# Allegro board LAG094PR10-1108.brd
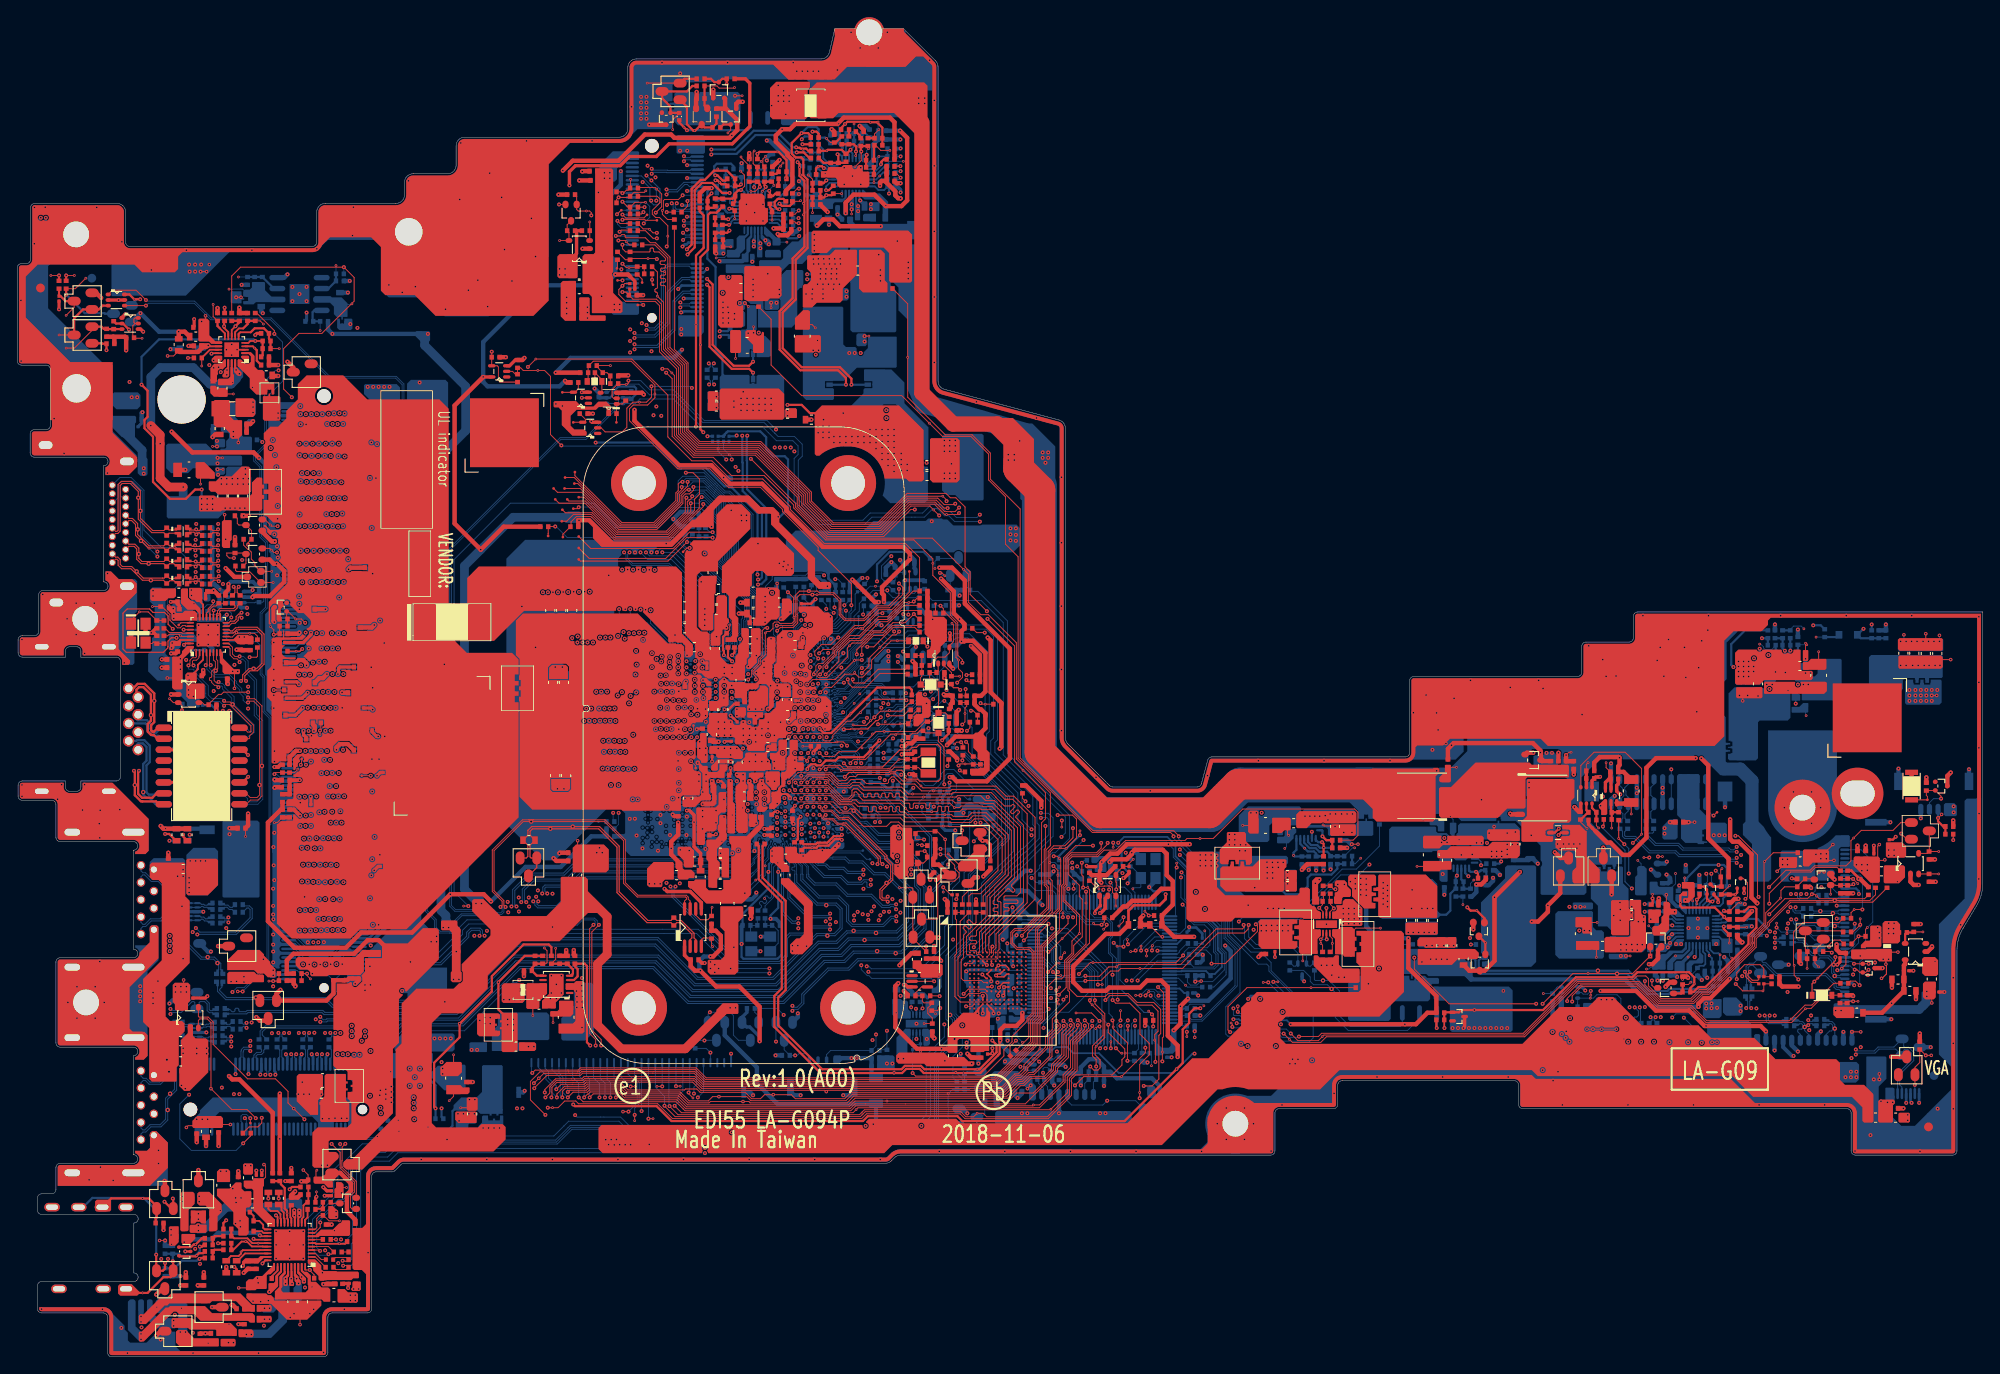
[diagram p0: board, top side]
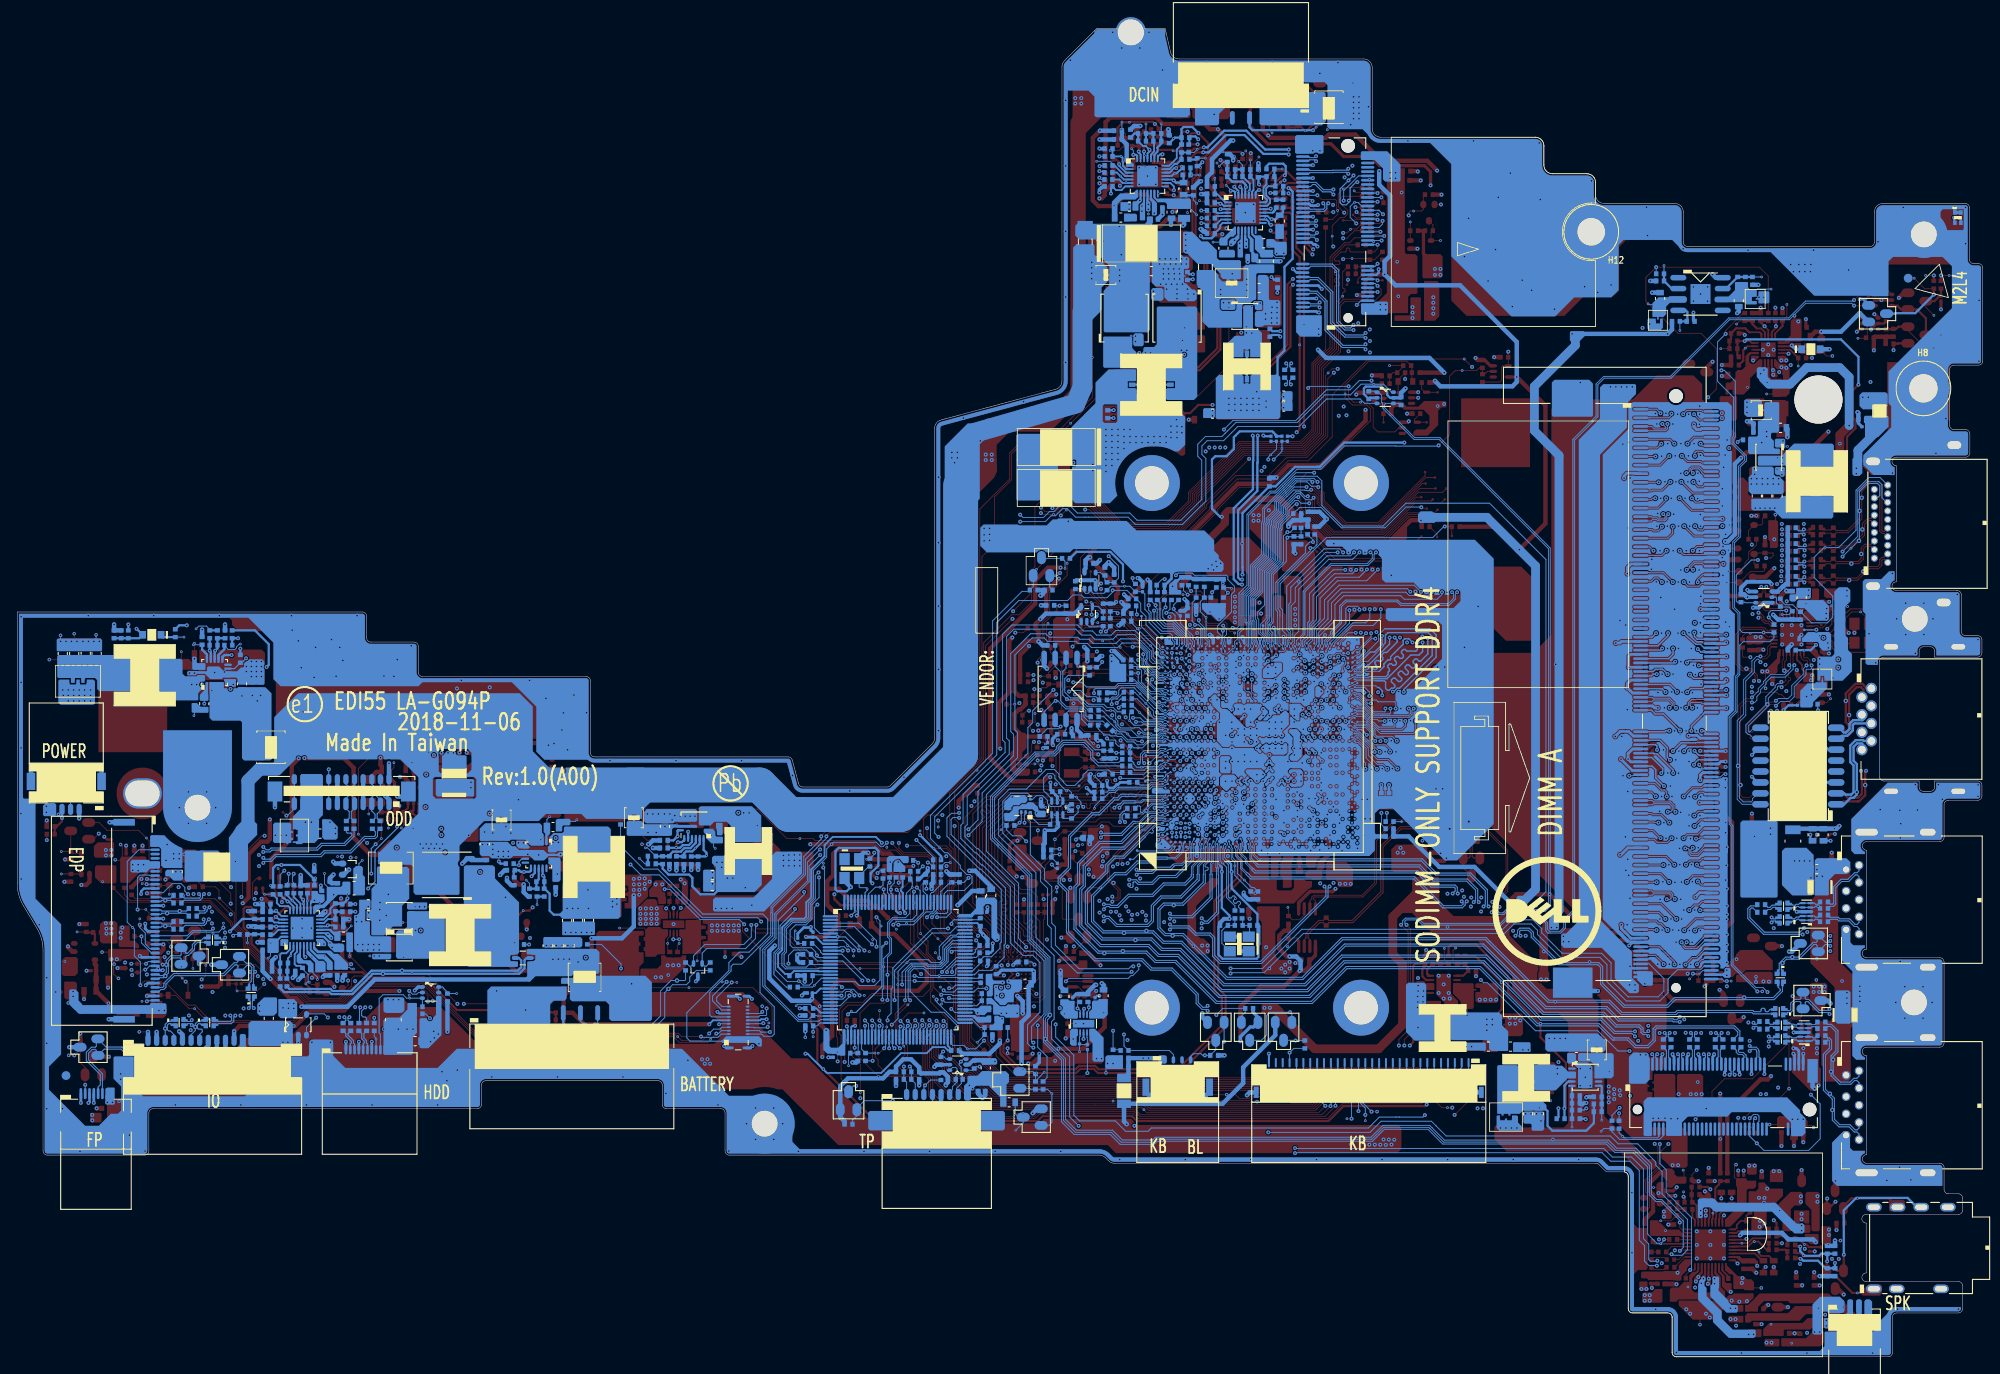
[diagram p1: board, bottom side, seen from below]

Outline 228.4 x 154.4 mm; copper layers: TOP, VCC, IN1, IN2, GND, BOTTOM. Coordinates in mm from the lower left corner of the outline.

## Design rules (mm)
net group CLK_SMB: nets CLK_SMB DAT_SMB
net group CLOCK: nets LPC_CLK_EC SUSCLK
net group DDR_M0_CLK0: nets DDR_M0_CLK0 DDR_M0_CLK#0
net group DDR_M0_CLK1: nets DDR_M0_CLK1 DDR_M0_CLK#1
net group DDR_M0_DQS0: nets DDR_M0_DQS0 DDR_M0_DQS#0
net group DDR_M0_DQS1: nets DDR_M0_DQS1 DDR_M0_DQS#1
net group DDR_M0_DQS2: nets DDR_M0_DQS2 DDR_M0_DQS#2
net group DDR_M0_DQS3: nets DDR_M0_DQS3 DDR_M0_DQS#3
net group DDR_M0_DQS4: nets DDR_M0_DQS4 DDR_M0_DQS#4
net group DDR_M0_DQS5: nets DDR_M0_DQS5 DDR_M0_DQS#5
net group DDR_M0_DQS6: nets DDR_M0_DQS6 DDR_M0_DQS#6
net group DDR_M0_DQS7: nets DDR_M0_DQS7 DDR_M0_DQS#7
net group DDR_RCOMP: nets DDR_M0_RCOMP DDR_M1_RCOMP
net group DIFFPAIR0: nets THM_SML1_CLK THM_SML1_DATA
net group DMIC: nets DMIC_CLK DMIC_DATA
net group EC_SMB_CK2: nets EC_SMB_CK2 EC_SMB_DA2
net group I2C_SCL_TP: nets I2C_SCL_TP I2C_SDA_TP
net group LAN_MDI2: nets LAN_MDIN2 LAN_MDIP2
net group LAN_MDI3: nets LAN_MDIN3 LAN_MDIP3
net group NCT7718_DX: nets NCT7718_DXN NCT7718_DXP
net group RJ45_MDI2: nets RJ45_MDIN2 RJ45_MDIP2
net group RJ45_MDI3: nets RJ45_MDIN3 RJ45_MDIP3
net group SENSE: nets VCC_VCGI_SENSE_N VCC_VCGI_SENSE_P
net group SOC_DP1_CTRL_CLK: nets SOC_DP1_CTRL_CLK SOC_DP1_CTRL_DATA
net group SOC_SMBCLK: nets SOC_SMBCLK SOC_SMBDATA
net group VNN_SENSE: nets VNN_SENSE VNN_SENSE_N
net group 15: nets DMIC_CLK_EDP EMMC_0_CLK HDA_BIT_CLK_R I2C_5_SCL REFCLK_CNV REFCLK_CNV_R SOC_SPI_CLK_R
net group AUDIO: nets HPOUT_L HPOUT_R LINE1-L_C LINE1-L_R N38607828
net group CNVI: nets CNVI_WGR_CLK_DN CNVI_WGR_CLK_DP CNVI_WGR_DATA0_DN CNVI_WGR_DATA0_DP CNVI_WGR_DATA1_DN CNVI_WGR_DATA1_DP CNVI_WT_CLK_DN CNVI_WT_CLK_DP CNVI_WT_DATA0_DN CNVI_WT_DATA0_DP CNVI_WT_DATA1_DN CNVI_WT_DATA1_DP
net group CNVI-OTHER: nets CLKREQ_CNV# CNV_BRI_PRX_DTX CNV_BRI_PTX_DRX CNV_RF_RESET# CNV_RGI_PRX_DTX CNV_RGI_PTX_DRX
net group DDR_CMD: nets DDR_M0_ACT# DDR_M0_ALERT# DDR_M0_BA0 DDR_M0_BA1 DDR_M0_BG0 DDR_M0_BG1 DDR_M0_CS#0 DDR_M0_CS#1 DDR_M0_MA0 DDR_M0_MA1 DDR_M0_MA2 DDR_M0_MA3 DDR_M0_MA4 DDR_M0_MA5 DDR_M0_MA6 DDR_M0_MA7 DDR_M0_MA8 DDR_M0_MA9 DDR_M0_MA10 DDR_M0_MA11 DDR_M0_MA12 DDR_M0_MA13 DDR_M0_MA14_WE# DDR_M0_MA15_CAS# DDR_M0_MA16_RAS#
net group DDR_CTL: nets DDR_M0_CKE0 DDR_M0_CKE1 DDR_M0_ODT0 DDR_M0_ODT1
net group DDR_D0: nets DDR_M0_D0 DDR_M0_D1 DDR_M0_D2 DDR_M0_D3 DDR_M0_D4 DDR_M0_D5 DDR_M0_D6 DDR_M0_D7
net group DDR_D1: nets DDR_M0_D8 DDR_M0_D9 DDR_M0_D10 DDR_M0_D11 DDR_M0_D12 DDR_M0_D13 DDR_M0_D14 DDR_M0_D15
net group DDR_D2: nets DDR_M0_D16 DDR_M0_D17 DDR_M0_D18 DDR_M0_D19 DDR_M0_D20 DDR_M0_D21 DDR_M0_D22 DDR_M0_D23
net group DDR_D3: nets DDR_M0_D24 DDR_M0_D25 DDR_M0_D26 DDR_M0_D27 DDR_M0_D28 DDR_M0_D29 DDR_M0_D30 DDR_M0_D31
net group DDR_D4: nets DDR_M0_D32 DDR_M0_D33 DDR_M0_D34 DDR_M0_D35 DDR_M0_D36 DDR_M0_D37 DDR_M0_D38 DDR_M0_D39
net group DDR_D5: nets DDR_M0_D40 DDR_M0_D41 DDR_M0_D42 DDR_M0_D43 DDR_M0_D44 DDR_M0_D45 DDR_M0_D46 DDR_M0_D47
net group DDR_D6: nets DDR_M0_D48 DDR_M0_D49 DDR_M0_D50 DDR_M0_D51 DDR_M0_D52 DDR_M0_D53 DDR_M0_D54 DDR_M0_D55
net group DDR_D7: nets DDR_M0_D56 DDR_M0_D57 DDR_M0_D58 DDR_M0_D59 DDR_M0_D60 DDR_M0_D61 DDR_M0_D62 DDR_M0_D63
net group DDR_REST: nets DDR_M0_DRAMRST#
net group DIFF_CLK: nets CLK_PCIE_N0 CLK_PCIE_N1 CLK_PCIE_N2 CLK_PCIE_P0 CLK_PCIE_P1 CLK_PCIE_P2
net group DMIC_CLK_EDP: nets DMIC_DATA_EDP
net group EDP: nets EDP_AUXN EDP_AUXN_C EDP_AUXP EDP_AUXP_C EDP_TXN0 EDP_TXN0_C EDP_TXN1 EDP_TXN1_C EDP_TXP0 EDP_TXP0_C EDP_TXP1 EDP_TXP1_C
net group EMMC: nets EMMC_0_CLK_R EMMC_0_CMD EMMC_0_CMD_R EMMC_0_DATA0 EMMC_0_DATA1 EMMC_0_DATA2 EMMC_0_DATA3 EMMC_0_DATA4 EMMC_0_DATA5 EMMC_0_DATA6 EMMC_0_DATA7 EMMC_0_RCLK EMMC_0_RCLK_R EMMC_0_RST EMMC_0_RST_R
net group HDA: nets HDA_BIT_CLK HDA_CODEC_SDIN0 HDA_RST# HDA_SDIN0 HDA_SDOUT HDA_SDOUT_R HDA_SYNC HDA_SYNC_R
net group HDMI: nets HDMI_CLKN HDMI_CLKP HDMI_L_CLKN HDMI_L_CLKP HDMI_L_TX_N0 HDMI_L_TX_N1 HDMI_L_TX_N2 HDMI_L_TX_P0 HDMI_L_TX_P1 HDMI_L_TX_P2 HDMI_TX_N0 HDMI_TX_N1 HDMI_TX_N2 HDMI_TX_P0 HDMI_TX_P1 HDMI_TX_P2 SOC_DP1_N0 SOC_DP1_N1 SOC_DP1_N2 SOC_DP1_N3 SOC_DP1_P0 SOC_DP1_P1 SOC_DP1_P2 SOC_DP1_P3
net group I2C_5_SCL: nets I2C_5_SDA
net group KB: nets KSI0 KSI1 KSI2 KSI3 KSI4 KSI5 KSI6 KSI7 KSO0 KSO1 KSO2 KSO3 KSO4 KSO5 KSO6 KSO7 KSO8 KSO9 KSO10 KSO11 KSO12 KSO13 KSO14 KSO15 KSO16
net group LAN: nets LAN_MDIN0 LAN_MDIN1 LAN_MDIP0 LAN_MDIP1
net group PCIE: nets PCIE_CRX_C_DTX_N5 PCIE_CRX_C_DTX_P5 PCIE_CRX_DTX_N0 PCIE_CRX_DTX_N1 PCIE_CRX_DTX_N2 PCIE_CRX_DTX_N3 PCIE_CRX_DTX_N4 PCIE_CRX_DTX_N5 PCIE_CRX_DTX_P0 PCIE_CRX_DTX_P1 PCIE_CRX_DTX_P2 PCIE_CRX_DTX_P3 PCIE_CRX_DTX_P4 PCIE_CRX_DTX_P5 PCIE_CTX_C_DRX_N0 PCIE_CTX_C_DRX_N1 PCIE_CTX_C_DRX_N2 PCIE_CTX_C_DRX_N3 PCIE_CTX_C_DRX_N4 PCIE_CTX_C_DRX_N5 PCIE_CTX_C_DRX_P0 PCIE_CTX_C_DRX_P1 PCIE_CTX_C_DRX_P2 PCIE_CTX_C_DRX_P3 PCIE_CTX_C_DRX_P4 PCIE_CTX_C_DRX_P5 PCIE_CTX_DRX_N0 PCIE_CTX_DRX_N1 PCIE_CTX_DRX_N2 PCIE_CTX_DRX_N3 PCIE_CTX_DRX_N4 PCIE_CTX_DRX_N5 PCIE_CTX_DRX_P0 PCIE_CTX_DRX_P1 PCIE_CTX_DRX_P2 PCIE_CTX_DRX_P3 PCIE_CTX_DRX_P4 PCIE_CTX_DRX_P5
net group RJ45: nets RJ45_MDIN0 RJ45_MDIN1 RJ45_MDIP0 RJ45_MDIP1
net group SATA: nets SATA_CRX_C_DTX_N0 SATA_CRX_C_DTX_N1 SATA_CRX_C_DTX_P0 SATA_CRX_C_DTX_P1 SATA_CRX_DTX_N0 SATA_CRX_DTX_N1 SATA_CRX_DTX_P0 SATA_CRX_DTX_P1 SATA_CTX_C_DRX_N0 SATA_CTX_C_DRX_N1 SATA_CTX_C_DRX_P0 SATA_CTX_C_DRX_P1 SATA_CTX_DRX_N0 SATA_CTX_DRX_N1 SATA_CTX_DRX_P0 SATA_CTX_DRX_P1
net group SMB: nets EC_SMB_CK1 EC_SMB_DA1 PCH_SMB_CLK PCH_SMB_DATA
net group SPI: nets SOC_SPI_CLK SOC_SPI_CS#0 SOC_SPI_CS#0_R SOC_SPI_IO2 SOC_SPI_IO2_0_R SOC_SPI_IO3 SOC_SPI_IO3_0_R SOC_SPI_SI SOC_SPI_SI_0_R SOC_SPI_SO SOC_SPI_SO_0_R
net group SPK: nets AUD_SPK_L+ AUD_SPK_L+_C AUD_SPK_L- AUD_SPK_L-_C AUD_SPK_R+ AUD_SPK_R+_C AUD_SPK_R- AUD_SPK_R-_C
net group SVID: nets SOC_SVID_ALERT# SOC_SVID_ALERT#_R SOC_SVID_CLK SOC_SVID_DAT
net group USB2.0: nets USB20_N0 USB20_N0_R USB20_N1 USB20_N1_R USB20_N2 USB20_N2_R USB20_N3 USB20_N4 USB20_N4_R USB20_N5 USB20_N5_R USB20_N6 USB20_N6_R USB20_N7 USB20_P0 USB20_P0_R USB20_P1 USB20_P1_R USB20_P2 USB20_P2_R USB20_P3 USB20_P4 USB20_P4_R USB20_P5 USB20_P5_R USB20_P6 USB20_P6_R USB20_P7
net group USB3.0: nets USB3_CRX_DTX_N0 USB3_CRX_DTX_N1 USB3_CRX_DTX_P0 USB3_CRX_DTX_P1 USB3_CRX_L_DTX_N0 USB3_CRX_L_DTX_N0_R USB3_CRX_L_DTX_N1 USB3_CRX_L_DTX_N1_R USB3_CRX_L_DTX_P0 USB3_CRX_L_DTX_P0_R USB3_CRX_L_DTX_P1 USB3_CRX_L_DTX_P1_R USB3_CTX_C_DRX_N0 USB3_CTX_C_DRX_N1 USB3_CTX_C_DRX_P0 USB3_CTX_C_DRX_P1 USB3_CTX_DRX_N0 USB3_CTX_DRX_N1 USB3_CTX_DRX_P0 USB3_CTX_DRX_P1 USB3_CTX_L_DRX_N0 USB3_CTX_L_DRX_N0_R USB3_CTX_L_DRX_N1 USB3_CTX_L_DRX_N1_R USB3_CTX_L_DRX_P0 USB3_CTX_L_DRX_P0_R USB3_CTX_L_DRX_P1 USB3_CTX_L_DRX_P1_R
nets with their own width: min track width 0.254; nets +3VALWP +5VALWP AVCORE1 AVCORE2 BATGONE BMON CCLIM COMP COMP_VCCGI COMP_VNN CSIN_CHG CSIP_CHG EN_1.05V EN_5V ENLDO_3V5V FB_1.05V FB_5V FB_5V_R FB_VCCGI FB_VNN HW_ACAV_IN ILMT_1.05V N17389450 N28483977 N28484391 N28484500 N28866422 N28866613 N38653708 N38993155 N38993903 N39173777 N39173785 N48572179 NTC_CHG RGND_VCCGI RGND_VNN RSET SET1_VCCGI SET1_VNN SET2_VCCGI SET2_VNN SET3_VCCGI SET3_VNN TSEN_VNN VBAT VCCGI_N03 VCCGI_N05 VCCGI_N09 VCCGI_N12 VCCGI_N17 VNN_N01 VNN_N02 VNN_N03 VNN_N04 VNN_N05 VNN_N10 VNN_N11 VNN_N13 VNN_N14 VREF_VNN VSEN_VCCGI VSEN_VNN
nets with their own width: min track width 0.381; nets +1.2V_DSI N28484416 N28484451
nets with their own width: min track width 0.508; nets +1.2V_DDR +1.2V_DDR_SOC +1.2V_MPHY +1.2V_PLL +1.2V_SOC +1.2V_USB2 +1.2V_VNNAON +1.05VS +1.05VS_SOC_SRAM +1.8V_EMMC +1.8V_PRIM +1.8VALW_SOC +2.5V_MEM +3V_EMMC +3VALW +3VALW_EC +3VALW_SOC +3VLP +3VS +3VS_CAM +5V_KB_BL +5VALW +5VS +19V_VIN +19VB +EC_VCCA +RTC_CELL +RTC_VCC +TP_VDD +TPAN_VDD +V_DDR_REFA +V_DDR_REFA_R +VCC_VCGI +VNN ASGATE BA BGATE CMSRC ECAGND GND MCT N18009640 N29179188 N29179534
nets with their own width: min track width 0.762; nets LG_1.2V LG_CHG LX_1.2V LX_CHG UG_1.2V UG_CHG
nets with their own width: min track width 1.016; nets +3V_DVDD +5V_AVDD +5V_HDMI +LCDVDD RING2 SLEEVE VDDREG
nets with their own width: min track width 1.524; nets +3VS_SSD +5V_HDD +5VS_ODD +LAN_VDD33
nets with their own width: min track width 2.032; nets +3.3V_WLAN +DCBAT_LCD +LCDVDD_LCD
nets with their own width: min track width 2.54; nets USB30_VCCA

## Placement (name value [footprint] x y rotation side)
C2  0.1U_0402_16V7K  [C_0402]  213.84 57.89 90 top
C3  1U_0201_6.3V6M  [C_0201]  215.74 57.89 90 top
C4  0.1U_0603_50V7K  [C_0603]  209.77 57.15 270 bottom
C5  1000P_0402_50V7K  [C_0402]  210.85 57.09 270 bottom
C6  0.1U_0402_16V7K  [C_0402]  207.54 52.13 0 bottom
C7  0.1U_0402_16V7K  [C_0402]  207.54 51.24 0 bottom
C8  0.1U_0402_16V7K  [C_0402]  209.32 50.6 0 bottom
C9  0.1U_0402_16V7K  [C_0402]  209.32 49.72 0 bottom
C10  0.1U_0402_16V7K  [C_0402]  209.32 52.76 0 bottom
C11  0.1U_0402_16V7K  [C_0402]  209.32 53.65 0 bottom
C12  82P_0402_50V8J  [C_0402]  214.79 57.89 90 top
C14  33P_0402_50V8J  [C_0402]  216.12 47.1 90 top
C15  4.7U_0402_6.3V6M  [C_0402]  215.24 47.1 90 top
C16  10P_0402_50V8J  [C_0402]  212.63 41.13 90 top
C17  1U_0201_6.3V_M  [C_0201]  217.52 59.55 90 top
C18  .1U_0402_16V7K  [C_0402]  110.08 32.01 270 bottom
C19  0.1U_0402_16V7K  [C_0402]  116.75 31.82 270 bottom
C21  0.1U_0402_16V7K  [C_0402]  78.25 46.16 0 top
C22  470P_0603_50V8J  [C_0603]  60.17 60.07 180 top
C23  2200P_0402_50V7K  [C_0402]  76.3 50.15 90 top
C26  10P_0402_50V8J  [C_0402]  124.51 32.25 180 bottom
C27  10P_0402_50V8J  [C_0402]  125.37 32.25 0 bottom
C34  .1U_0402_16V7K  [C_0402]  99.27 33.78 0 bottom
C35  1U_0201_6.3V6M  [C_0201]  222.73 42.41 0 top
C37  0.1U_0402_16V7K  [C_0402]  217.64 28.89 0 top
C39  1U_0201_6.3V6M  [C_0201]  211.81 46.96 270 top
C41  1U_0201_6.3V6M  [C_0201]  4.86 123.33 270 top
C49  68P_0201_50V8J  [C_0201]  214.47 47.14 90 top
C225  1U_0201_6.3V_M  [C_0201]  156.33 44.61 180 top
C231  10U_0402_6.3V6M  [C_0402]  156.45 43.81 180 top
C232  1U_0201_6.3V_M  [C_0201]  146.15 47.7 270 top
C233  10U_0402_6.3V6M  [C_0402]  145.07 47.75 270 top
C234  10U_0402_6.3V6M  [C_0402]  154.59 52.94 90 top
C235  10U_0402_6.3V6M  [C_0402]  149.89 54.01 0 top
C967  470P_0402_50V7K  [C_0402]  152.57 46.16 90 top
C976  470P_0402_50V7K  [C_0402]  151.68 46.16 90 top
C979  0.1U_0402_10V7K  [C_0402]  153.53 52.95 180 top
C980  0.1U_0402_10V7K  [C_0402]  150.77 52.95 0 top
C981  0.1U_0201_10V6K  [C_0201]  150.92 47.04 270 top
C982  0.1U_0201_10V6K  [C_0201]  153.34 47.04 270 top
C983  1U_0201_6.3V6M  [C_0201]  219.82 44.89 180 top
CA2  .1U_0402_16V7K  [C_0402]  34.26 7.12 270 top
CA3  10U_0603_10V6M  [C_0603]  31.97 7.11 270 top
CA25  1U_0603_16V7  [C_0603]  24.29 11.17 270 top
CA26  10U_0402_6.3V6M  [C_0402]  31.85 17.61 90 top
CA27  1000P_0402_50V7K  [C_0402]  26.39 4.71 270 top
CA28  1000P_0402_50V7K  [C_0402]  26.4 5.58 180 top
CA43  68P_0201_50V8J  [C_0201]  30.16 6.89 270 top
CA44  68P_0201_50V8J  [C_0201]  36.1 9.11 270 top
CA45  68P_0201_50V8J  [C_0201]  27.78 20.53 90 top
CA46  68P_0201_50V8J  [C_0201]  37.09 19.3 180 top
CA47  10P_0201_50V8J  [C_0201]  35.02 6.89 270 top
CA48  10P_0201_50V8J  [C_0201]  38.58 9.11 270 top
CA49  10P_0201_50V8J  [C_0201]  28.42 20.53 90 top
CA50  10P_0201_50V8J  [C_0201]  37.09 18.73 180 top
CA51  0.1U_0402_25V6  [C_0402]  25.69 19.99 90 top
CA52  0.1U_0402_25V6  [C_0402]  31.85 20.43 90 top
CA53  0.1U_0402_25V6  [C_0402]  19.59 9.22 270 top
CA474  .1U_0402_16V7K  [C_0402]  30.9 7.12 270 top
CA475  .1U_0402_16V7K  [C_0402]  27.8 18.92 180 top
CA476  1000P_0402_50V7K  [C_0402]  21.24 1.76 90 top
CA477  10U_0402_6.3V6M  [C_0402]  38.36 14.47 0 top
CA478  0.1U_0402_16V7K  [C_0402]  34.65 17.14 180 top
CA479  10U_0402_6.3V6M  [C_0402]  26.55 15.81 0 top
CA480  1000P_0402_50V7K  [C_0402]  23.43 2.73 180 top
CA481  10U_0603_10V6M  [C_0603]  28.04 17.84 180 top
CA482  10U_0402_6.3V6M  [C_0402]  28.66 9.1 0 top
CA483  10U_0402_6.3V6M  [C_0402]  37.82 9.39 270 top
CA484  10U_0402_6.3V6M  [C_0402]  26.88 10.22 90 top
CA485  .1U_0402_16V7K  [C_0402]  36.86 9.41 270 top
CA486  6.8P_0402_50V  [C_0402]  38.5 11.3 0 top
CA487  33P_0402_50V8J  [C_0402]  39.42 12.19 180 top
CA488  .1U_0402_16V7K  [C_0402]  33.83 18.85 180 top
CA489  2.2U_0402_6.3V6M  [C_0402]  27.47 14.6 180 top
CA490  .1U_0402_16V7K  [C_0402]  35.91 14.46 90 top
CA491  10P_0402_50V8J  [C_0402]  38.5 10.41 0 top
CA492  .1U_0402_16V7K  [C_0402]  27.78 11.13 270 top
CA493  10U_0402_6.3V6M  [C_0402]  39.25 13.39 180 top
CA494  10U_0603_10V6M  [C_0603]  33.18 7.11 270 top
CA495  10U_0402_6.3V6M  [C_0402]  28.66 8.21 0 top
CA496  1U_0603_16V7  [C_0603]  25.5 9.77 90 top
CA497  680P_0402_50V8J  [C_0402]  22.59 16.7 180 top
CA498  100P_0402_50V8J  [C_0402]  18.07 11.98 90 bottom
CA499  680P_0402_50V8J  [C_0402]  19.52 15.81 0 top
CA500  10U_0603_10V6M  [C_0603]  29.18 17.71 90 top
CA501  680P_0402_50V8J  [C_0402]  22.59 15.81 180 top
CA502  680P_0402_50V8J  [C_0402]  19.52 16.7 0 top
CA503  10U_0603_10V6M  [C_0603]  30.39 17.71 90 top
CA504  100P_0402_50V8J  [C_0402]  17.18 10.3 270 bottom
CC1  10P_0402_50V8J  [C_0402]  102.03 67.75 180 bottom
CC2  10P_0402_50V8J  [C_0402]  102.66 77.2 180 bottom
CC3  22P_0201_50V  [C_0201]  108.68 71.41 270 bottom
CC4  0.1U_0402_25V6K  [C_0402]  104.25 92.26 180 bottom
CC5  0.1U_0201_10V6K  [C_0201]  107.82 83.37 0 top
CC6  0.1U_0402_16V7K  [C_0402]  105.77 73.85 90 top
CC7  0.1U_0402_25V6K  [C_0402]  98.94 85.53 0 bottom
CC8  0.1U_0201_10V6K  [C_0201]  97.63 88.95 90 bottom
CC9  0.1U_0402_16V7K  [C_0402]  103.53 72 0 top
CC10  0.47U_0402_6.3V6K  [C_0402]  106.51 57.22 270 top
CC11  1U_0402_6.3V6K  [C_0402]  103.72 58.54 0 top
CC12  1U_0402_6.3V6K  [C_0402]  103.46 60.83 0 top
CC13  18P_0402_50V8J  [C_0402]  104.29 68.52 270 top
CC14  18P_0402_50V8J  [C_0402]  104.29 69.45 90 top
CC15  68P_0201_50V8J  [C_0201]  93.25 86.15 90 bottom
CC16  10P_0402_50V8J  [C_0402]  84.29 50.16 0 bottom
CC17  10P_0402_50V8J  [C_0402]  88.63 50.16 180 bottom
CC18  0.1U_0402_10V7K  [C_0402]  99.4 62.89 180 bottom
CC19  0.1U_0402_10V7K  [C_0402]  99.4 63.77 180 bottom
CC20  0.1U_0402_10V7K  [C_0402]  80.17 114.75 270 bottom
CC21  0.1U_0402_10V7K  [C_0402]  81.12 114.75 270 bottom
CC22  0.1U_0402_16V7K  [C_0402]  80.04 95.39 270 bottom
CC23  1U_0402_6.3V6K  [C_0402]  85.24 61.97 180 top
CC24  1U_0402_6.3V6K  [C_0402]  85.24 62.86 180 top
CC25  1U_0402_6.3V6K  [C_0402]  85.23 66.23 180 top
CC26  22U_0603_6.3V6M  [C_0603]  85.19 65.15 180 top
CC27  1U_0402_6.3V6K  [C_0402]  82.14 64.1 0 top
CC28  22U_0603_6.3V6M  [C_0603]  78.01 57.59 0 top
CC29  1U_0402_6.3V6K  [C_0402]  81.45 85.78 180 top
CC30  1U_0402_6.3V6K  [C_0402]  79.79 68.44 90 top
CC31  22U_0603_6.3V6M  [C_0603]  81.95 88.07 180 top
CC32  22U_0603_6.3V6M  [C_0603]  81.95 86.86 180 top
CC33  1U_0402_6.3V6K  [C_0402]  79.62 73.03 270 top
CC34  2.2U_0402_6.3V6M  [C_0402]  80.54 84.83 0 top
CC35  1U_0402_6.3V6K  [C_0402]  87.64 75.98 180 top
CC36  1U_0402_6.3V6K  [C_0402]  84.54 76.16 0 top
CC37  22U_0603_6.3V6M  [C_0603]  89.25 87.69 180 top
CC38  12P_0402_50V8J  [C_0402]  86.58 77.77 90 top
CC39  1U_0402_6.3V6K  [C_0402]  85.31 68.52 270 top
CC40  1U_0402_6.3V6K  [C_0402]  86.27 68.52 270 top
CC41  22U_0603_6.3V6M  [C_0603]  85.29 51.87 180 top
CC42  1U_0402_6.3V6K  [C_0402]  75.9 57.15 0 top
CC43  1U_0402_6.3V6K  [C_0402]  80.09 65.02 0 top
CC44  1U_0402_6.3V6K  [C_0402]  83.66 76.84 270 top
CC45  22U_0603_6.3V6M  [C_0603]  75.92 56 0 top
CC46  1U_0402_6.3V6K  [C_0402]  80.95 66.29 180 top
CC47  1U_0402_6.3V6K  [C_0402]  79.52 59.81 0 top
CC48  1U_0402_6.3V6K  [C_0402]  82.08 65.41 90 top
CC49  22U_0603_6.3V6M  [C_0603]  82.39 56.19 180 top
CC50  22U_0603_6.3V6M  [C_0603]  81 57.4 0 top
CC51  22U_0603_6.3V6M  [C_0603]  81 58.61 0 top
CC52  0.5P_0402_50V8  [C_0402]  81.67 61.5 180 top
CC53  1U_0402_6.3V6K  [C_0402]  80.93 67.55 90 top
CC54  1U_0402_6.3V6K  [C_0402]  89.73 68.45 180 top
CC55  1U_0402_6.3V6K  [C_0402]  89.73 69.34 180 top
CC56  1U_0402_6.3V6K  [C_0402]  86.83 69.85 0 top
CC57  22U_0603_6.3V6M  [C_0603]  90.27 71.28 180 top
CC58  0.5P_0402_50V8  [C_0402]  64.94 58.61 180 top
CC59  0.1U_0402_25V6K  [C_0402]  64.03 57.65 0 top
CC60  0.1U_0402_25V6K  [C_0402]  76.81 62.85 90 top
CC61  0.1U_0402_25V6K  [C_0402]  79.03 64.82 90 top
CC62  0.1U_0402_25V6K  [C_0402]  80.37 78.27 270 top
CC63  0.1U_0402_25V6K  [C_0402]  76.93 83.32 270 top
CC64  22U_0603_6.3V6M  [C_0603]  63.79 66.86 90 top
CC65  22U_0603_6.3V6M  [C_0603]  62.26 79.12 270 top
CC66  22U_0603_6.3V6M  [C_0603]  63.53 79.12 270 top
CC67  22U_0603_6.3V6M  [C_0603]  64.49 87.5 270 top
CC68  22U_0603_6.3V6M  [C_0603]  62.52 66.86 90 top
CC69  22U_0603_6.3V6M  [C_0603]  63.22 87.5 270 top
CC70  22U_0603_6.3V6M  [C_0603]  77.97 64.23 90 top
CC71  22U_0603_6.3V6M  [C_0603]  61.95 87.5 270 top
CC73  1U_0402_6.3V6K  [C_0402]  75.98 83.32 270 top
CC74  1U_0402_6.3V6K  [C_0402]  89.04 86.61 180 top
CC75  1U_0402_6.3V6K  [C_0402]  84.54 77.07 0 top
CC76  1U_0402_6.3V6K  [C_0402]  85.11 85.34 0 top
CC77  1U_0402_6.3V6K  [C_0402]  87.64 76.89 180 top
CC78  22U_0603_6.3V6M  [C_0603]  84.81 87.69 0 top
CC79  22U_0603_6.3V6M  [C_0603]  84.81 86.42 0 top
CC80  1U_0402_6.3V6K  [C_0402]  85.2 74.61 180 top
CC81  1U_0402_6.3V6K  [C_0402]  87.22 68.52 270 top
CC82  1U_0402_6.3V6K  [C_0402]  87.92 65.32 90 top
CC83  1U_0402_6.3V6K  [C_0402]  89.01 67.56 180 top
CC84  1U_0402_6.3V6K  [C_0402]  81.81 67.62 0 top
CC85  22U_0603_6.3V6M  [C_0603]  90.01 57.91 180 top
CC86  0.5P_0402_50V8  [C_0402]  88.6 58.99 0 top
CC88  0.1U_0402_25V6K  [C_0402]  91.07 69.58 270 top
CC89  0.1U_0402_16V7K  [C_0402]  107.74 79.56 180 top
CC90  0.1U_0402_16V7K  [C_0402]  102.02 91.77 270 bottom
CC91  0.1U_0402_25V6K  [C_0402]  104.81 72.19 0 bottom
CC92  0.1U_0402_10V7K  [C_0402]  70.71 112.09 270 top
CC93  0.1U_0402_25V6K  [C_0402]  69.83 114.04 180 top
CC95  100P_0402_50V8J  [C_0402]  68.47 60.51 0 bottom
CC96  0.1U_0402_25V6K  [C_0402]  78.39 98.24 270 bottom
CC272  1U_0402_6.3V6K  [C_0402]  77.58 77.91 270 top
CD1  10U_0402_6.3V6M  [C_0402]  36.75 43.78 90 top
CD2  10U_0402_6.3V6M  [C_0402]  38 43.78 90 top
CD3  1U_0201_6.3V_M  [C_0201]  38.95 43.99 90 top
CD4  1U_0201_6.3V_M  [C_0201]  39.71 43.99 90 top
CD5  1U_0201_6.3V_M  [C_0201]  28.34 44.78 270 top
CD6  10U_0402_6.3V6M  [C_0402]  27.26 45.27 270 top
CD7  10U_0402_6.3V6M  [C_0402]  26.05 45.27 270 top
CD8  10U_0402_6.3V6M  [C_0402]  24.85 45.27 270 top
CD9  0.1U_0402_16V7K~D  [C_0402]  40.8 46.02 90 top
CD10  2.2U_0402_6.3V6M  [C_0402]  41.82 46.02 90 top
CD11  1U_0201_6.3V_M  [C_0201]  41.82 72.89 180 top
CD12  1U_0201_6.3V_M  [C_0201]  39.64 75.43 0 top
CD13  1U_0201_6.3V_M  [C_0201]  42.51 68.52 270 top
CD14  1U_0201_6.3V_M  [C_0201]  30.49 83.05 0 top
CD15  1U_0201_6.3V_M  [C_0201]  30.68 76.58 0 top
CD16  1U_0201_6.3V_M  [C_0201]  33.54 64.19 0 top
CD17  1U_0201_6.3V_M  [C_0201]  30.68 78.48 0 top
CD18  1U_0201_6.3V_M  [C_0201]  42.19 57.6 270 top
CD19  10U_0402_6.3V6M  [C_0402]  33.65 86.93 0 top
CD20  10U_0402_6.3V6M  [C_0402]  32.67 71.83 0 top
CD21  10U_0402_6.3V6M  [C_0402]  40.03 70.54 180 top
CD22  10U_0402_6.3V6M  [C_0402]  39.84 83.88 90 top
CD23  10U_0402_6.3V6M  [C_0402]  30.25 74.61 0 top
CD24  10U_0402_6.3V6M  [C_0402]  30.32 80.7 0 top
CD25  10U_0402_6.3V6M  [C_0402]  40.03 80.19 180 top
CD26  10U_0402_6.3V6M  [C_0402]  33.68 78.37 0 top
CD27  330U_D2_2V_Y  [C_D2]  47.32 85.4 0 top
CD28  0.1U_0402_16V7K~D  [C_0402]  31.66 67.05 180 top
CD29  0.1U_0402_16V7K~D  [C_0402]  30.49 84.07 0 top
CD30  0.022U_0402_25V7K  [C_0402]  30.82 63.63 270 top
CD31  0.1U_0402_16V7K~D  [C_0402]  41.31 91.75 180 top
CD32  0.1U_0402_16V7K~D  [C_0402]  30.75 69.72 0 top
CD33  0.1U_0402_16V7K~D  [C_0402]  39.35 77.21 180 top
CE1  .1U_0402_16V7K  [C_0402]  130.72 35.31 270 bottom
CE2  0.047U_0402_25V7K  [C_0402]  135.91 38.48 0 bottom
CE3  10P_0402_50V8J  [C_0402]  121.05 55.18 0 bottom
CE4  .1U_0402_16V7K  [C_0402]  122.84 55.16 90 bottom
CE5  .1U_0402_16V7K  [C_0402]  136.17 45.84 0 bottom
CE6  .1U_0402_16V7K  [C_0402]  135.97 44.32 0 bottom
CE7  .1U_0402_16V7K  [C_0402]  138.67 44.32 180 bottom
CE8  .1U_0402_16V7K  [C_0402]  116.57 47.81 180 bottom
CE9  .1U_0402_16V7K  [C_0402]  132 39.11 180 top
CE10  0.1U_0201_10V6K  [C_0201]  116.33 51.7 180 bottom
CE11  0.1U_0201_10V6K  [C_0201]  136 42.3 0 bottom
CE12  0.1U_0201_10V6K  [C_0201]  133.57 35.4 270 bottom
CE13  0.1U_0201_10V6K  [C_0201]  135.92 48.79 90 bottom
CE16  0.1U_0201_10V6K  [C_0201]  116.18 39.33 90 bottom
CE17  100P_0402_50V8J  [C_0402]  118.96 35.62 0 bottom
CE18  680P_0402_50V7K  [C_0402]  116.49 51 270 bottom
CE19  .1U_0402_16V7K  [C_0402]  119.8 55.16 90 bottom
CE20  100P_0402_50V8J  [C_0402]  123.72 55.56 0 bottom
CE21  100P_0402_50V8J  [C_0402]  121.97 56.07 180 bottom
CE23  22P_0201_50V  [C_0201]  137.7 48.67 270 bottom
CE35  1U_0201_6.3V6M  [C_0201]  125.31 56.99 0 top
CE36  1U_0201_6.3V6M  [C_0201]  125.85 52.45 0 top
CE37  1U_0201_6.3V6M  [C_0201]  129.19 56.43 90 top
CG27  0.1U_0402_16V7K  [C_0402]  22.4 89.85 180 top
CG28  0.1U_0402_16V7K  [C_0402]  22.4 90.74 180 top
CG29  0.1U_0402_16V7K  [C_0402]  22.4 91.75 180 top
CG30  0.1U_0402_16V7K  [C_0402]  22.4 92.64 180 top
CG31  0.1U_0402_16V7K  [C_0402]  22.4 95.5 180 top
CG32  0.1U_0402_16V7K  [C_0402]  22.4 96.39 180 top
CG33  0.1U_0402_16V7K  [C_0402]  22.4 93.66 180 top
CG34  0.1U_0402_16V7K  [C_0402]  22.4 94.55 180 top
CG46  0.1U_0201_10V6K  [C_0201]  13.46 108.14 0 bottom
CG47  4.7U_0402_6.3V6M  [C_0402]  13.55 108.96 0 bottom
CL5  .1U_0402_16V7K  [C_0402]  24.42 79.76 270 top
CL6  .1U_0402_16V7K  [C_0402]  18.64 82.91 270 top
CL7  .1U_0402_16V7K  [C_0402]  26.13 83.08 270 top
CL8  .1U_0402_16V7K  [C_0402]  19.54 87.78 180 top
CL9  1U_0201_6.3V_M  [C_0201]  20.95 75.75 0 bottom
CL10  12P_0402_50V8J  [C_0402]  16.23 84.69 90 top
CL11  12P_0402_50V8J  [C_0402]  16.23 83.83 270 top
CL12  0.01U_0402_50V7K  [C_0402]  26.53 61.46 180 top
CL13  33P_1206_2KV8J  [C_1206]  22.07 61.27 270 bottom
CL16  1U_0201_6.3V6M  [C_0201]  21.31 88.13 0 top
CL18  0.1U_0402_10V7K  [C_0402]  21.17 88.96 0 top
CL24  4.7U_0402_6.3V6M  [C_0402]  27.09 83.08 270 top
CL25  4.7U_0402_6.3V6M  [C_0402]  18.33 81.08 180 top
CL26  0.1U_0402_10V7K  [C_0402]  25.9 88.53 270 top
CL27  0.1U_0402_10V7K  [C_0402]  25.01 88.53 270 top
CL28  1U_0201_6.3V_M  [C_0201]  20.76 83.37 0 bottom
CL29  .1U_0402_16V7K  [C_0402]  18.33 80.13 180 top
CL30  .1U_0402_16V7K  [C_0402]  22.13 88.12 90 bottom
CL31  .1U_0402_16V7K  [C_0402]  20.53 79.18 0 top
CL32  .1U_0402_16V7K  [C_0402]  18.83 86 90 top
CLRP1  SHORT PADS  [SHORTPADS]  104.11 60.32 0 bottom
CLRP2  SHORT PADS  [SHORTPADS]  104.21 57.41 0 top
CM1  4.7U_0402_6.3V6M  [C_0402]  113 41.54 270 bottom
CM2  0.1U_0402_25V6  [C_0402]  106.59 45.39 90 top
CM3  4.7U_0402_6.3V6M  [C_0402]  111.98 35.7 270 top
CM4  0.1U_0402_25V6  [C_0402]  111.1 35.7 270 top
CM5  0.1U_0402_25V6  [C_0402]  111.15 45.91 0 bottom
CM6  0.1U_0402_16V7K  [C_0402]  104.38 41.97 180 top
CM7  0.1U_0402_16V7K  [C_0402]  105.63 45.39 90 top
CM8  22P_0402_50V8J  [C_0402]  108.1 51.68 0 top
CM9  68P_0201_50V8J  [C_0201]  113.76 41.12 270 bottom
CM10  68P_0201_50V8J  [C_0201]  112.75 35.78 270 top
CM11  1U_0201_6.3V6M  [C_0201]  103.16 41.17 90 bottom
CM17  220P_0402_50V7K  [C_0402]  21.18 86.62 270 bottom
CM26  10P_0402_50V8J  [C_0402]  25.29 97.79 0 top
CM27  10P_0402_50V8J  [C_0402]  25.31 93.45 90 top
CM28  1U_0201_6.3V6M  [C_0201]  105.76 41.17 90 bottom
CM29  1000P_0402_50V7K  [C_0402]  104.94 41.26 90 bottom
CM30  1000P_0402_50V7K  [C_0402]  103.98 41.26 90 bottom
CS3  0.01U_0402_16V7K  [C_0402]  190.53 38.81 270 bottom
CS4  0.01U_0402_16V7K  [C_0402]  189.65 38.81 270 bottom
CS5  0.01U_0402_16V7K  [C_0402]  187.8 38.81 270 bottom
CS6  0.01U_0402_16V7K  [C_0402]  188.69 38.81 270 bottom
CS12  10U_0603_10V6M  [C_0603]  182.88 36.7 180 bottom
CS13  1000P_0402_50V7K  [C_0402]  182.23 38.03 180 bottom
CS14  0.1U_0402_25V6K  [C_0402]  182.23 38.98 180 bottom
CS16  0.1U_0402_10V7K  [C_0402]  37.12 36.9 270 bottom
CS18  0.01U_0402_16V7K  [C_0402]  186.24 61.39 90 bottom
CS26  10U_0603_10V6M  [C_0603]  193.92 60.83 180 bottom
CS30  0.1U_0402_10V7K  [C_0402]  36.23 36.9 270 bottom
CS31  0.1U_0402_10V7K  [C_0402]  34.07 36.9 270 bottom
CS32  0.1U_0402_10V7K  [C_0402]  33.18 36.9 270 bottom
CS33  0.1U_0402_10V7K  [C_0402]  31.09 36.9 270 bottom
CS34  0.1U_0402_10V7K  [C_0402]  30.2 36.9 270 bottom
CS35  0.1U_0402_10V7K  [C_0402]  28.1 36.9 270 bottom
CS36  0.1U_0402_10V7K  [C_0402]  28.99 36.9 270 bottom
CS38  22U_0603_6.3V6M  [C_0603]  36.04 30.6 180 top
CS39  47U_0805_6.3V6M  [C_0805]  36.32 32.13 180 top
CS40  22U_0603_6.3V6M  [C_0603]  21.94 26.92 270 top
CS41  1U_0201_6.3V_M  [C_0201]  35.31 29.46 180 top
CS42  10U_0402_6.3V6M  [C_0402]  23.4 27.01 270 top
CS43  1000P_0402_50V7K~D  [C_0402]  35.61 28.51 180 top
CS44  0.1U_0402_25V6K~D  [C_0402]  20.86 26.87 270 top
CS109  0.1U_0402_25V6K  [C_0402]  193.59 62.16 180 top
CS110  0.01U_0402_16V7K  [C_0402]  189.26 61.39 90 bottom
CS111  0.01U_0402_16V7K  [C_0402]  190.15 61.39 90 bottom
CS112  1000P_0402_50V7K  [C_0402]  193.59 62.16 180 bottom
CS113  0.01U_0402_16V7K  [C_0402]  187.13 61.39 90 bottom
CS114  0.1U_0402_25V6K  [C_0402]  109.32 63.1 90 bottom
CS115  10U_0402_6.3V6M  [C_0402]  113.37 62.95 90 bottom
CT14  220P_0402_50V7K  [C_0402]  212.7 54.81 270 top
CU16  .1U_0402_16V7K  [C_0402]  25.95 38.1 180 bottom
CU17  22U_0603_6.3V6M  [C_0603]  18.3 34.35 0 top
CU18  22U_0603_6.3V6M  [C_0603]  18.58 56.7 0 top
CU19  22U_0603_6.3V6M  [C_0603]  18.3 36.7 0 top
CU20  4.7U_0402_6.3V6M  [C_0402]  18.18 33.27 0 top
CU21  1U_0201_6.3V6M  [C_0201]  19.83 41.71 0 top
CU22  100U_A_6.3VM_R70M  [C_A]  16.61 39.75 180 bottom
CU24  .1U_0402_16V7K  [C_0402]  26.21 51.68 180 bottom
CU25  4.7U_0402_6.3V6M  [C_0402]  17.56 57.01 90 top
CU26  22U_0603_6.3V6M  [C_0603]  18.58 56.7 0 bottom
CU28  100U_A_6.3VM_R70M  [C_A]  18.32 54.61 0 bottom
CU29  .1U_0402_16V7K  [C_0402]  25.95 38.98 180 bottom
CU30  .1U_0402_16V7K  [C_0402]  26.21 52.57 180 bottom
CU31  1U_0201_6.3V6M  [C_0201]  197.82 41.4 0 bottom
CU32  22U_0603_6.3V6M  [C_0603]  199.17 38.64 90 bottom
CW1  4.7P_0402_50V8C  [C_0402]  103.53 73.6 0 top
CW4  .1U_0402_16V7K  [C_0402]  64.66 121.79 0 top
CW5  10U_0402_6.3V6M  [C_0402]  64.66 122.8 0 top
CW6  10U_0402_6.3V6M  [C_0402]  67.53 136.77 180 top
CW7  .1U_0402_16V7K  [C_0402]  68.04 121.67 270 top
CW8  .1U_0402_16V7K  [C_0402]  67.42 137.85 180 top
CW9  10P_0402_50V8J  [C_0402]  67.09 121.67 270 top
CW10  .1U_0402_16V7K  [C_0402]  64.66 120.84 0 top
D3  -  [BAT54C-7-F_SOT23-3]  207.78 49.53 270 top
D4  -  [BAT54C-7-F_SOT23-3]  222.18 61.15 90 top
D5  -  [RB551V-30_SOD323-2]  208.56 42.03 0 top
D11  -  [AZC199-02SPR7G_SOT23-3]  207.27 46.6 90 bottom
D12  CEST523NC5VB 3P C/A SOT-523  [TVNST52302AB0_SOT523-3]  215.85 45.19 270 top
D14  CEST523NC5VB 3P C/A SOT-523  [TVNST52302AB0_SOT523-3]  29.92 87.17 90 top
DA1  -  [L03ESDL5V0CC3-2_SOT23-3]  23.81 5.77 90 top
DA2  -  [L03ESDL5V0CC3-2_SOT23-3]  17.15 2.98 270 top
DA5  CEST23LC3V3B 3P C/A SOT-23  [AZ5123-02SPR7G_SOT23-3]  21.05 20.47 180 top
DA6  -  [AZC199-02SPR7G_SOT23-3]  204.66 45.59 270 bottom
DA7  -  [BAT54CW_SOT323-3]  37.49 17.84 90 top
DA8  -  [L03ESDL5V0CC3-2_SOT23-3]  17.15 7.92 0 top
DA9  -  [L03ESDL5V0CC3-2_SOT23-3]  17.17 19.32 180 top
DA10  BAT54ATB_SOT-523-3  [BAT54ATB_SOT523-3]  20.14 12.25 90 top
DC1  -  [BAS40C_SOT23-3]  108.4 56 270 top
DC2  -  [CH751H-40PT_SOD323-2]  107.06 74.87 270 top
DC3  -  [CH751H-40PT_SOD323-2]  107.31 78.16 180 top
DC4  RB751S-40 SOD-523 PANJIT  [RB751S40T1G_SOD523-2]  105.28 83.24 180 top
DC5  RB751S-40 SOD-523 PANJIT  [RB751S40T1G_SOD523-2]  67.94 113.41 180 top
DC6  CEST23LC3V3B 3P C/A SOT-23  [AZ5123-02SPR7G_SOT23-3]  32.08 114.49 270 top
DD1  CEST23LC3V3B 3P C/A SOT-23  [AZ5123-02SPR7G_SOT23-3]  24.57 47.75 270 top
DD2  CEST23LC3V3B 3P C/A SOT-23  [AZ5123-02SPR7G_SOT23-3]  29.16 39.34 0 top
DE1  -  [CK0402101V05_0402-2]  137.08 46.79 180 bottom
DI1  -  [BAW56W_SOT323-3]  26.73 90.67 270 top
EC2901  1000P_0402_50V7K  [C_0402]  221.84 65.83 90 top
EC2902  .1U_0402_16V7K  [C_0402]  224.05 61.65 0 top
EC3001  .1U_0402_16V7K  [C_0402]  89.77 35.05 180 bottom
EC3002  .1U_0402_16V7K  [C_0402]  99.27 34.73 0 bottom
ED2901  -  [TVNST52302AB0_SOT523-3]  224.28 66.35 270 top
EU2605  -  [AZ1045-04F_DFN2510P10E-10-9]  20.04 50.75 90 bottom
EU2606  -  [AZ1045-04F_DFN2510P10E-10-9]  20.32 36.71 90 bottom
EU2607  -  [AZC199-02SPR7G_SOT23-3]  18.8 41.42 90 bottom
EU2608  -  [AZC199-02SPR7G_SOT23-3]  21.2 48.06 270 bottom
EU2701  -  [AZC199-02SPR7G_SOT23-3]  221.1 36 270 bottom
EU4012  -  [AZC199-02SPR7G_SOT23-3]  219.55 34.88 180 top
F1  1.5A_24V_SMD1812P150TF-24  [F_SMD1812P150TF-24]  202.59 56.95 0 bottom
F3  0.5A_13.2V_MF-NSMF050-2  [F_MF-NSMF050-2]  99.79 32.42 270 bottom
F5  1A_65V_T0603FF1000TM  [F_T0603FF1000TM]  217.29 48.5 270 top
FD1  FIDUCAL  [FIDUCIAL_C40M80]  2.7 124.26 0 top
FD2  FIDUCAL  [FIDUCIAL_C40M80]  222.09 26.73 0 top
FD3  FIDUCAL  [FIDUCIAL_C40M80]  8.67 125.41 180 bottom
FD4  FIDUCAL  [FIDUCIAL_C40M80]  222.73 32.7 180 bottom
FI1  1.5A_6V_1206L150PR~D  [F_1206L150PR]  11.98 108.58 90 bottom
H1  HOLEA  [H_3P0]  6.85 130.5 0 top
H2  HOLEA  [H_3P0-G]  99 154 0 top
H4  HOLEA  [H_3P0-G]  7.9 85.8 0 top
H5  HOLEA  [H_3P0-G]  8 41.2 0 top
H6  HOLEA  [H_3P0-G]  207.45 63.85 0 top
H7  HOLEA  [H_3P0-G]  141.55 27.1 0 top
H8  HOLEA  [H_3P3]  6.9 112.6 0 top
H12  HOLEA  [H_3P2]  45.5 130.8 0 top
H13  HOLEA  [H_3P0X4P0]  213.85 65.5 90 top
H14  HOLEA  [H_5P6N]  19.1 111.3 0 top
HCPU1  HOLEA  [H_3P9]  72.25 101.59 0 top
HCPU2  HOLEA  [H_3P9]  96.55 101.59 0 top
HCPU3  HOLEA  [H_3P9]  72.25 40.59 0 top
HCPU4  HOLEA  [H_3P9]  96.55 40.59 0 top
JDB1  HRS_BM20B-20DS-0P4V  [HRS_BM20B-20DS-0P4V_20P-T]  145.71 37.12 90 bottom
JDIMM1  DEREN_40-42271-26001RHF  [LOTES_ADDR0206-P001A02_260P]  39.75 110.68 90 bottom
JEDP1  ACES_51540-04001-P01  [ACES_51540-04001-P01_40P]  212.37 60.45 270 bottom
JFP1  ACES_51522-00801-001  [ACES_51522-00801-001_8P]  221 30.6 180 bottom
JHDD1  ACES_51625-01201-001  [ACES_51625-01201-001_12P]  190.2 35.7 180 bottom
JHDMI1  CONCR_099AKAC19NBLCNF  [ACON_HMRF6-AK120C_19P-T]  11.05 92.35 90 bottom
JHP1  YUQIU_PJ753-F07J1BE-B  [YUQIU_PJ753-F07J1BE-B_7P-T]  12.65 7.9 90 bottom
JIOB1  ACES_51524-0160N-001  [ACES_51524-0160N-001_16P]  213.2 36.8 180 bottom
JKB1  HEFEN_AFB02-S30F1A-HF  [HEFEN_AFB02-S30F1A-HF_30P-T]  59.75 34.2 180 bottom
JKBBL1  ACES_51575-00401-001  [ACES_51575-00401-001_4P]  95.05 34.52 180 bottom
JODD1  ACES_50673-0120N-001  [ACES_50673-0120N-001_12P-T]  185.2 64.3 180 bottom
JP5  -  [JUMP_43X79]  196.74 60.61 180 bottom
JP10  -  [JUMP_43X79]  38.03 31.49 0 top
JP11  2MM  [JUMP_43X39]  18.64 79.26 270 bottom
JP12  -  [JUMP_43X118]  57.59 77.72 0 top
JP33  JUMP  [JUMP_43X118]  149.11 49.33 180 top
JP50  JUMP  [JUMP_43X118]  155.25 48 0 top
JPWR1  JXT_FP226H-004S1AM  [JXT_FP226H-004S1AM_4P]  221.2 63.65 0 bottom
JRJ45  SANTA_130460-N  [SINGA_2RJ3076-078211F_8P-T]  12.95 77.72 90 bottom
JSPK1  ACES_50224-00401-001  [ACES_50224-00401-001_4P]  16.4 5.88 180 bottom
JSSD1  LCN_DAN05-67306-0103  [LCN_DAN05-67306-0103_75P]  39.38 34.03 180 bottom
JTP1  ACES_51524-0080N-001  [ACES_51524-0080N-001_8P]  125.05 30.5 180 bottom
JUSB1  ACON_TARAN-9R1391  [ACON_TARAN-9R1391_9P]  15.88 56.65 90 bottom
JUSB2  ACON_TARAN-9R1391  [ACON_TARAN-9R1391_9P]  15.88 32.75 90 bottom
JWLAN1  LOTES_APCI0136-P001A  [LOTES_APCI0136-P001A_75P]  79.03 121.55 90 bottom
L3  MCM1012B900F06BP_4P  [INPAQ_MCM1012B900F06BP_4P]  205.09 48.2 0 bottom
L4  MCM1012B900F06BP_4P  [INPAQ_MCM1012B900F06BP_4P-NPM]  201.45 41.72 90 bottom
L5  BLM15PX221SN1D_2P  [MURAT_BLM15PX221SN1D_2P]  36.72 11.3 180 top
LA1  BLM15PX330SN1D_2P  [MURAT_BLM15PX330SN1D_2P]  21.71 14.85 0 top
LA2  0_0402_5%  [R_0402]  22.72 13.01 180 top
LA3  0_0402_5%  [R_0402]  22.72 11.49 180 top
LA13  BLM15PX330SN1D_2P  [MURAT_BLM15PX330SN1D_2P]  18.47 14.85 0 top
LE1  BLM15BD121SN1D_2P  [MURAT_BLM15BD121SN1D_2P]  114.61 39.3 0 bottom
LE2  BLM15BD121SN1D_2P  [MURAT_BLM15BD121SN1D_2P]  115.46 40.44 180 bottom
LED1  LTW-295DSKS-5A_YEL-WHITE~D  [LED_LTW-295DSKS-5A_4P]  3.25 133.05 270 bottom
LI1  HCM1012GH900BP_4P  [INPAQ_HCM1012GH900BP_4P-NPM]  18.65 94.42 0 top
LI2  HCM1012GH900BP_4P  [INPAQ_HCM1012GH900BP_4P-NPM]  18.65 96.26 0 top
LI3  HCM1012GH900BP_4P  [INPAQ_HCM1012GH900BP_4P-NPM]  18.65 92.52 0 top
LI4  HCM1012GH900BP_4P  [INPAQ_HCM1012GH900BP_4P-NPM]  18.65 90.56 0 top
LU7  HCM1012GH900BP_4P  [INPAQ_HCM1012GH900BP_4P-NPM]  22.52 52.13 0 bottom
LU8  HCM1012GH900BP_4P  [INPAQ_HCM1012GH900BP_4P-NPM]  22.78 36.7 0 bottom
LU9  MCM1012B900F06BP_4P  [INPAQ_MCM1012B900F06BP_4P]  23.28 44.69 270 bottom
LU10  MCM1012B900F06BP_4P  [INPAQ_MCM1012B900F06BP_4P]  23.03 39.88 0 bottom
LU11  HCM1012GH900BP_4P  [INPAQ_HCM1012GH900BP_4P-NPM]  22.78 38.29 0 bottom
LU12  HCM1012GH900BP_4P  [INPAQ_HCM1012GH900BP_4P-NPM]  22.52 50.55 0 bottom
LU13  MCM1012B900F06BP_4P  [INPAQ_MCM1012B900F06BP_4P]  210.21 39.11 180 bottom
LU14  MCM1012B900F06BP_4P  [INPAQ_MCM1012B900F06BP_4P]  206.65 39.11 180 bottom
NOREF  -  []  58.41 72.27 270 top
NOREF#2  -  []  7.4 86.8 0 top
NOREF#3  -  []  195.61 32.06 0 top
NOREF#4  -  []  213.85 65.5 0 top
NOREF#5  -  []  141.55 27.1 180 top
NOREF#6  -  []  65.41 15.36 0 top
NOREF#7  -  []  48.25 101.02 270 top
NOREF#8  -  []  96.55 40.59 0 top
NOREF#9  -  []  7.4 86.8 0 top
NOREF#10  -  []  -99.79 120.33 0 top
NOREF#11  -  []  214.97 74.29 0 top
NOREF#12  -  []  72.25 101.59 0 top
NOREF#13  -  []  7.9 85.8 0 top
NOREF#14  -  []  7.4 86.8 0 top
NOREF#15  -  []  7.4 86.8 0 top
NOREF#16  -  []  7.4 86.8 0 top
NOREF#17  -  []  6.85 130.5 0 top
NOREF#18  -  []  93.44 -29.21 0 top
NOREF#19  -  []  7.4 86.8 0 top
NOREF#20  -  []  49.37 71.05 0 top
NOREF#21  -  []  99 154 0 top
NOREF#22  -  []  8 41.2 90 top
NOREF#23  -  []  72.25 40.59 0 top
NOREF#24  -  []  45.5 130.8 0 top
NOREF#25  -  []  56.61 107.44 0 top
NOREF#26  -  []  207.45 63.85 0 top
NOREF#27  -  []  6.9 112.6 90 top
NOREF#28  -  []  96.55 101.59 0 top
NOREF#29  -  []  50.15 52.5 180 bottom
NOREF#30  -  []  115.01 75.57 90 bottom
NOREF#31  -  []  114.21 54.73 180 bottom
PBATT1  -  [ACES_50458-01001-P01_10P-T]  172.95 39.98 180 bottom
PC1  1000P_0402_50V7K  [C_0402]  90.84 147.87 90 top
PC2  100P_0402_50V8J  [C_0402]  89.89 147.87 90 top
PC3  1000P_0402_50V7K  [C_0402]  93.44 147.87 90 top
PC4  100P_0402_50V8J  [C_0402]  94.4 147.87 90 top
PC11  0.01U_0402_25V7K  [C_0402]  163.08 47.07 90 bottom
PC12  1000P_0402_50V7K  [C_0402]  164.88 43.7 270 bottom
PC13  .1U_0402_16V7K  [C_0402]  183.5 63.3 180 top
PC14  .1U_0402_16V7K  [C_0402]  194.42 42.41 180 top
PC15  10P_0402_25V8J  [C_0402]  91.79 147.87 90 top
PC301  1000P_0402_50V7K  [C_0402]  172.37 60.27 270 top
PC302  2200P_0402_50V7K  [C_0402]  172.37 60.27 270 bottom
PC303  4.7U_0603_25V6K  [C_0603]  174.09 60.32 270 bottom
PC304  4.7U_0603_25V6K  [C_0603]  174.09 60.32 270 top
PC305  0.1U_0402_25V6  [C_0402]  171.48 60.27 270 bottom
PC306  1000P_0402_50V7K  [C_0402]  171.48 60.27 270 top
PC307  0.1U_0402_10V7K  [C_0402]  164.5 62.24 270 bottom
PC308  4.7U_0402_6.3V6M  [C_0402]  165.83 55.49 270 bottom
PC309  680P_0603_50V7K  [C_0603]  166.15 57.02 90 top
PC310  22U_0603_6.3V6M  [C_0603]  161.96 51.46 270 top
PC311  22U_0603_6.3V6M  [C_0603]  163.23 51.46 270 bottom
PC312  22U_0603_6.3V6M  [C_0603]  161.96 51.46 270 bottom
PC313  22U_0603_6.3V6M  [C_0603]  164.5 51.43 270 bottom
PC314  22U_0603_6.3V6M  [C_0603]  163.23 51.46 270 top
PC315  1000P_0402_25V8J  [C_0402]  167.99 54.43 270 bottom
PC316  22U_0603_6.3V6M  [C_0603]  164.5 51.43 270 top
PC317  1U_0402_25V6K  [C_0402]  169.74 55.65 0 top
PC501  1000P_0402_50V7K  [C_0402]  201.08 77.52 90 top
PC502  2200P_0402_50V7K  [C_0402]  201.08 77.52 90 bottom
PC503  10U_0603_25V6M  [C_0603]  202.28 77.53 90 bottom
PC504  10U_0603_25V6M  [C_0603]  202.28 77.53 90 top
PC505  0.1U_0402_25V6  [C_0402]  200.12 77.52 90 bottom
PC506  1000P_0402_50V7K  [C_0402]  200.12 77.52 90 top
PC507  0.1U_0402_10V7K  [C_0402]  207.81 75.74 90 bottom
PC508  4.7U_0402_6.3V6M  [C_0402]  207.81 81.85 180 top
PC509  680P_0603_50V7K  [C_0603]  207.87 80.32 180 top
PC510  22U_0603_6.3V6M  [C_0603]  221.78 81.06 90 bottom
PC511  22U_0603_6.3V6M  [C_0603]  223.11 81.06 90 bottom
PC512  22U_0603_6.3V6M  [C_0603]  223.11 81.06 90 top
PC513  22U_0603_6.3V6M  [C_0603]  220.44 81.08 90 bottom
PC514  22U_0603_6.3V6M  [C_0603]  221.78 81.06 90 top
PC515  4.7U_0402_6.3V6M  [C_0402]  206.92 82.79 90 bottom
PC516  4.7U_0402_6.3V6M  [C_0402]  217.14 84.46 270 bottom
PC517  1000P_0402_25V8J  [C_0402]  205.14 83.55 90 bottom
PC518  22U_0603_6.3V6M  [C_0603]  219.17 81.08 90 top
PC519  22U_0603_6.3V6M  [C_0603]  219.17 81.08 90 bottom
PC520  22U_0603_6.3V6M  [C_0603]  220.44 81.08 90 top
PC1201  22U_0603_6.3V6M  [C_0603]  57.25 36.06 0 top
PC1202  22U_0603_6.3V6M  [C_0603]  56.74 36.06 0 bottom
PC1203  22U_0603_6.3V6M  [C_0603]  55.6 36.06 180 bottom
PC1204  22U_0603_6.3V6M  [C_0603]  59.91 40.95 0 top
PC1205  0.1U_0402_10V7K  [C_0402]  63.92 45.7 90 top
PC1206  22P_0402_50V8J  [C_0402]  61.06 46.62 270 top
PC1207  680P_0402_50V7K  [C_0402]  62.26 39.86 90 top
PC1801  22U_0603_6.3V6M  [C_0603]  46.52 34.86 0 bottom
PC1802  22U_0603_6.3V6M  [C_0603]  51.6 28.95 270 bottom
PC1803  22U_0603_6.3V6M  [C_0603]  52.87 28.95 270 bottom
PC1804  22U_0603_6.3V6M  [C_0603]  52.87 28.95 270 top
PC1805  0.1U_0402_10V7K  [C_0402]  47.74 30.35 180 bottom
PC1806  680P_0402_50V7K  [C_0402]  52.23 31.03 90 top
PC1807  22P_0402_50V8J  [C_0402]  45.2 28.51 180 bottom
PC2501  22U_0603_6.3V6M  [C_0603]  37.5 122.33 90 bottom
PC2502  22U_0603_6.3V6M  [C_0603]  28.36 123.5 270 bottom
PC2503  0.1U_0402_10V6K  [C_0402]  37.04 125.09 0 bottom
PC2504  2.2U_0402_6.3V6M  [C_0402]  34.4 120.39 180 bottom
PC2505  0.01U_0402_25V7K  [C_0402]  28.48 124.63 90 bottom
PCB01  0.1U_0402_25V6  [C_0402]  178.2 68.35 90 top
PCB02  0.01U_0402_25V7K  [C_0402]  191.37 50.73 180 top
PCB03  0.1U_0402_25V6  [C_0402]  191.42 52.71 270 bottom
PCB04  0.033U_0402_25V7K  [C_0402]  189.87 52.57 270 top
PCB05  1U_0402_25V6K  [C_0402]  191.44 50.88 180 bottom
PCB06  0.47U_0402_25V6K  [C_0402]  189.76 47.56 0 bottom
PCB07  1U_0402_25V6K  [C_0402]  192.06 55.25 270 bottom
PCB08  2.2U_0402_6.3V6M  [C_0402]  193.01 54.17 270 bottom
PCB09  10P_0402_50V8J  [C_0402]  198.97 51.75 0 bottom
PCB10  2200P_0402_25V7K  [C_0402]  200.82 50.91 90 bottom
PCB11  0.033U_0402_25V7K  [C_0402]  199.88 49.94 270 top
PCB12  560P_0402_50V7K  [C_0402]  198.97 49.97 0 bottom
PCB13  0.1U_0402_25V6  [C_0402]  200.82 49.13 90 bottom
PCB14  0.1U_0402_25V6  [C_0402]  198.97 48.19 0 bottom
PCB15  0.1U_0402_25V6  [C_0402]  196.93 45.78 0 bottom
PCB16  0.22U_0402_25V6K  [C_0402]  197.87 44.84 0 bottom
PCB17  1U_0402_25V6K  [C_0402]  197.01 44.84 180 bottom
PCB18  0.47U_0402_25V6K  [C_0402]  194.34 45.02 180 bottom
PCB19  2.2U_0402_6.3V6M  [C_0402]  190.34 45.28 270 bottom
PCB20  10U_0603_25V6M  [C_0603]  186.89 51.38 0 bottom
PCB21  10U_0603_25V6M  [C_0603]  186.89 51.38 0 top
PCB22  10U_0603_25V6M  [C_0603]  186.89 52.61 0 bottom
PCB23  10U_0603_25V6M  [C_0603]  186.89 52.61 0 top
PCB24  0.1U_0402_25V7K  [C_0402]  186.84 49.33 0 bottom
PCB25  2200P_0402_25V7K  [C_0402]  186.81 50.3 0 bottom
PCB26  1000P_0402_25V8J  [C_0402]  186.84 49.33 0 top
PCB27  1000P_0402_25V8J  [C_0402]  186.81 50.3 0 top
PCB28  0.1U_0402_25V7K  [C_0402]  173.85 57.76 270 bottom
PCB29  680P_0603_50V7K  [C_0603]  183.5 47.77 0 top
PCB30  10U_0603_25V6M  [C_0603]  166.76 47.07 90 top
PCB31  10U_0603_25V6M  [C_0603]  166.76 47.07 90 bottom
PCB32  10U_0603_25V6M  [C_0603]  165.49 47.07 90 top
PCB33  10U_0603_25V6M  [C_0603]  165.49 47.07 90 bottom
PCB34  10U_0603_25V6M  [C_0603]  164.22 47.07 90 bottom
PCB35  0.1U_0402_25V7K  [C_0402]  163.08 47.07 90 top
PCB36  0.047U_0402_25V7K  [C_0402]  198.94 53.74 270 top
PCB37  1U_0402_25V6K  [C_0402]  191.17 55.06 270 bottom
PCB70  15U_B2_25VM_R100M  [C_B2]  177.63 66.44 270 bottom
PCG01  10U_0402_6.3V6M  [C_0402]  96.25 133.6 180 bottom
PCG02  0.22U_0603_25V7K  [C_0603]  94.27 132.38 90 bottom
PCG03  0.1U_0402_25V6  [C_0402]  94.52 141.11 90 bottom
PCG04  0.1U_0402_25V6  [C_0402]  96.3 139.86 270 top
PCG05  0.1U_0402_25V6  [C_0402]  95.41 138.82 270 top
PCG06  10U_0402_6.3V6M  [C_0402]  100.05 141.54 0 bottom
PCG07  0.47U_0402_6.3V6K  [C_0402]  91.73 135.96 270 bottom
PCG08  0.1U_0402_25V6  [C_0402]  99.03 141.78 90 bottom
PCG09  0.1U_0402_25V6  [C_0402]  101.02 136.69 0 top
PCG10  0.1U_0402_10V6K  [C_0402]  102.04 140.46 180 bottom
PCG11  330P_0402_50V8J  [C_0402]  97.24 141.35 0 bottom
PCG12  68P_0402_50V8J  [C_0402]  95.46 141.35 0 bottom
PCG13  0.22U_0402_16V7K  [C_0402]  98.54 132.46 180 bottom
PCG14  0.1U_0402_10V6K  [C_0402]  93.1 140.03 90 bottom
PCG15  10U_0603_25V6M  [C_0603]  98.4 126.3 180 top
PCG16  10U_0603_25V6M  [C_0603]  97.32 126.23 180 bottom
PCG17  680P_0402_50V7K  [C_0402]  91.6 121.39 90 top
PCG18  0.1U_0402_25V6  [C_0402]  97.07 125.15 180 bottom
PCG19  2200P_0402_50V7K  [C_0402]  96.76 132.27 180 bottom
PCG20  33U_D2_25VM_R60M  [C_D2]  100.96 129.45 180 bottom
PCG100  22U_0603_6.3V6M  [C_0603]  89.67 82.74 0 top
PCG101  22U_0603_6.3V6M  [C_0603]  80.7 73.07 270 top
PCG102  22U_0603_6.3V6M  [C_0603]  89.44 75.69 90 top
PCG103  22U_0603_6.3V6M  [C_0603]  88.81 74.61 0 top
PCG104  22U_0603_6.3V6M  [C_0603]  86.52 70.9 0 top
PCG105  22U_0603_6.3V6M  [C_0603]  82.05 74.55 90 top
PCG106  22U_0603_6.3V6M  [C_0603]  80.83 74.52 90 top
PCG107  22U_0603_6.3V6M  [C_0603]  93 108.96 180 top
PCG108  22U_0603_6.3V6M  [C_0603]  105 102.42 0 top
PCG109  22U_0603_6.3V6M  [C_0603]  105 103.69 0 top
PCG110  330U_D2_2V_Y  [C_D2]  104.47 105.79 0 bottom
PCG111  330U_D2_2V_Y  [C_D2]  104.47 101.02 0 bottom
PCG112  1U_0201_6.3V6M  [C_0201]  87.07 74.61 180 top
PCG113  1U_0201_6.3V6M  [C_0201]  86.37 73.72 180 top
PCG114  1U_0201_6.3V6M  [C_0201]  85.12 70.65 270 top
PCG115  1U_0201_6.3V6M  [C_0201]  83.57 71.56 180 top
PCG116  1U_0201_6.3V6M  [C_0201]  88.5 81.06 180 top
PCG117  1U_0201_6.3V6M  [C_0201]  88.5 81.95 180 top
PCG118  1U_0201_6.3V6M  [C_0201]  83.66 73.24 90 top
PCG119  1U_0201_6.3V6M  [C_0201]  88.15 79.37 180 top
PCG120  1U_0201_6.3V6M  [C_0201]  88.5 82.84 180 top
PCG121  1U_0201_6.3V6M  [C_0201]  91.09 86.98 90 top
PCG122  1U_0201_6.3V6M  [C_0201]  90.46 76.87 270 top
PCG123  1U_0201_6.3V6M  [C_0201]  88.15 80.26 180 top
PCG124  1000P_0402_50V7K  [C_0402]  98.15 128.39 180 top
PCG125  1000P_0402_50V7K  [C_0402]  98.15 127.44 180 top
PCG126  1000P_0402_50V7K  [C_0402]  84.76 125.34 180 top
PCG127  1000P_0402_50V7K  [C_0402]  84.82 123.19 180 top
PCH01  0.1U_0402_25V6  [C_0402]  155.16 61.58 90 bottom
PCH02  2200P_0402_50V7K  [C_0402]  154.21 61.58 90 bottom
PCH03  10U_0603_25V6M  [C_0603]  153.13 60.96 90 bottom
PCH04  10U_0603_25V6M  [C_0603]  153.13 60.96 90 top
PCH05  22U_0603_6.3V6M  [C_0603]  146.91 54.73 0 bottom
PCH06  22U_0603_6.3V6M  [C_0603]  146.91 56 0 top
PCH07  22U_0603_6.3V6M  [C_0603]  146.91 54.73 0 top
PCH08  22U_0603_6.3V6M  [C_0603]  146.91 56 0 bottom
PCH09  0.1U_0402_25V6  [C_0402]  152.8 60.04 0 bottom
PCH10  1U_0402_10V6K  [C_0402]  152.8 59.15 0 bottom
PCH11  1U_0402_10V6K  [C_0402]  150.94 58.17 270 bottom
PCH12  0.1U_0402_10V6K  [C_0402]  146.85 61.76 90 bottom
PCH13  680P_0603_50V7K  [C_0603]  147.61 62.03 0 top
PCH14  330P_0402_50V7K  [C_0402]  154.2 57.32 0 bottom
PCH15  1000P_0402_50V7K  [C_0402]  155.16 61.58 90 top
PCH16  1000P_0402_50V7K  [C_0402]  154.21 61.58 90 top
PCM01  0.1U_0402_25V6  [C_0402]  25.74 107.5 0 bottom
PCM02  2200P_0402_50V7K  [C_0402]  25.74 108.45 0 bottom
PCM03  10U_0603_25V6M  [C_0603]  24.22 108.01 180 bottom
PCM04  10U_0603_25V6M  [C_0603]  23.53 108.63 270 top
PCM05  22U_0603_6.3V6M  [C_0603]  23.85 99.37 90 top
PCM06  22U_0603_6.3V6M  [C_0603]  26.26 99.37 90 top
PCM07  22U_0603_6.3V6M  [C_0603]  23.85 99.37 90 bottom
PCM08  22U_0603_6.3V6M  [C_0603]  25.05 99.37 90 bottom
PCM09  22U_0603_6.3V6M  [C_0603]  26.26 99.37 90 bottom
PCM10  22U_0603_6.3V6M  [C_0603]  25.05 99.37 90 top
PCM11  680P_0402_50V7K  [C_0402]  22.64 102.37 270 top
PCM12  0.1U_0402_10V7K  [C_0402]  22.77 112.5 90 top
PCM13  2.2U_0402_6.3V6M  [C_0402]  21.45 117.53 180 top
PCM14  2.2U_0402_6.3V6M  [C_0402]  21.38 119.69 180 top
PCM15  0.1U_0402_10V7K  [C_0402]  25.82 120.44 90 top
PCM16  0.1U_0402_10V7K  [C_0402]  26.77 120.44 90 top
PCM17  220P_0402_25V8J  [C_0402]  29.43 117.22 180 top
PCM18  .1U_0402_16V7K  [C_0402]  28.34 116.26 0 top
PCM19  0.033U_0402_16V7K  [C_0402]  28.34 115.31 0 top
PCM20  22U_0603_6.3V6M  [C_0603]  28.23 114.1 0 top
PCM22  1000P_0402_50V7K  [C_0402]  25.74 107.5 0 top
PCM23  1000P_0402_50V7K  [C_0402]  25.74 108.45 0 top
PCZ01  2200P_0402_50V7K  [C_0402]  84.76 125.34 180 bottom
PCZ02  0.1U_0402_25V6  [C_0402]  84.82 123.19 180 bottom
PCZ03  0.1U_0402_25V6  [C_0402]  89.04 131.07 0 top
PCZ04  82P_0402_50V8J  [C_0402]  85.11 137.22 0 bottom
PCZ05  330P_0402_50V8J  [C_0402]  86.89 137.22 0 bottom
PCZ06  10U_0603_25V6M  [C_0603]  84.81 124.26 180 top
PCZ07  10U_0603_25V6M  [C_0603]  84.81 124.26 180 bottom
PCZ08  0.1U_0402_10V6K  [C_0402]  90.15 134.17 180 bottom
PCZ09  0.22U_0402_16V7K  [C_0402]  87.17 128.2 180 bottom
PCZ10  0.47U_0402_6.3V6K  [C_0402]  81.7 129.33 90 bottom
PCZ11  0.1U_0402_10V6K  [C_0402]  82.32 137.22 0 bottom
PCZ12  680P_0402_50V7K  [C_0402]  83.41 119.05 90 top
PCZ13  0.22U_0603_25V7K  [C_0603]  82.84 129.47 0 bottom
PCZ14  10U_0402_6.3V6M  [C_0402]  84.5 127.95 0 bottom
PCZ15  10U_0402_6.3V6M  [C_0402]  89.24 135.19 0 bottom
PCZ16  0.1U_0402_25V6  [C_0402]  84.17 137.14 90 bottom
PCZ17  0.1U_0402_25V6  [C_0402]  87.79 138.92 90 bottom
PCZ18  0.1U_0402_25V6  [C_0402]  81.11 133.76 90 top
PCZ19  0.1U_0402_25V6  [C_0402]  83.42 134.96 0 top
PCZ100  22U_0603_6.3V6M  [C_0603]  83.71 69.85 270 top
PCZ101  22U_0603_6.3V6M  [C_0603]  78.27 85.97 180 top
PCZ102  22U_0603_6.3V6M  [C_0603]  84.06 79.4 270 top
PCZ103  22U_0603_6.3V6M  [C_0603]  88.81 109.66 0 top
PCZ104  22U_0603_6.3V6M  [C_0603]  81.95 110.49 180 top
PCZ105  22U_0603_6.3V6M  [C_0603]  81.95 110.49 180 bottom
PCZ106  1U_0201_6.3V6M  [C_0201]  80.74 70.39 270 top
PCZ107  1U_0201_6.3V6M  [C_0201]  80.15 79.47 90 top
PCZ108  1U_0201_6.3V6M  [C_0201]  84.51 80.83 0 top
PCZ109  1U_0201_6.3V6M  [C_0201]  80.15 81.25 270 top
PCZ110  22U_0603_6.3V6M  [C_0603]  78.27 84.7 180 top
PCZ111  22U_0603_6.3V6M  [C_0603]  79.4 82.51 180 top
PCZ112  22U_0603_6.3V6M  [C_0603]  84.45 82.35 0 top
PCZ113  22U_0603_6.3V6M  [C_0603]  88.81 109.66 0 bottom
PCZ114  22U_0603_6.3V6M  [C_0603]  81.06 81.66 90 top
PCZ115  22U_0603_6.3V6M  [C_0603]  84.49 84.26 0 top
PCZ116  22U_0603_6.3V6M  [C_0603]  78.27 87.24 180 top
PCZ117  22U_0603_6.3V6M  [C_0603]  82.07 69.94 270 top
PCZ118  22U_0603_6.3V6M  [C_0603]  81.95 111.76 180 bottom
PCZ119  22U_0603_6.3V6M  [C_0603]  81.95 111.76 180 top
PD1  -  [TVNST52302AB0_SOT523-3]  75.41 143.25 180 top
PD2  -  [BAV99W_SC70-3]  81.53 148.2 0 top
PD3  -  [BAV99W_SC70-3]  82.9 143.28 180 top
PD5  -  [L03ESDL5V0CG3-2_SOT-523-3]  149.31 44.33 0 bottom
PD6  -  [L03ESDL5V0CG3-2_SOT-523-3]  168.18 39.56 270 top
PD14  AZ4024-02S_SOT23  [PJSOT24C_SOT23-3]  180.27 58 180 top
PD501  -  [RB751V-40_SOD323-2]  211.69 83.94 0 bottom
PD502  -  [RB751V-40_SOD323-2]  21.04 117.15 180 bottom
PDB01  -  [LRB715FT1G_SOT323-3]  188.7 56.7 90 bottom
PDB13  AZ4024-02S_SOT23  [PJSOT24C_SOT23-3]  184.3 58 180 top
PH1  100K_0402_1%_B25/50 4250K  [R_0402]  86.85 59.62 180 top
PHG1  10K_0402_1%_B25/50 3370K  [R_0402]  101.7 110.05 270 bottom
PHG2  100K_0402_1%_B25/50 4250K  [R_0402]  81.95 125.23 270 bottom
PHZ1  1K_0402_5%_TSM0B102J3652RE  [R_0402]  82.84 118.6 90 bottom
PHZ2  100K_0402_1%_B25/50 4250K  [R_0402]  92.43 125.2 90 bottom
PJP1  JUMP_43X79  [JUMP_43X79-NPM]  91.66 145.5 0 top
PJP2  JUMP_43X79  [JUMP_43X79-NPM]  76.53 145.28 180 bottom
PJP3  JUMP_43X79  [JUMP_43X79-NPM]  162.47 44.68 270 bottom
PJP301  JUMP_43X39  [JUMP_43X39-NPM]  172.12 62.87 270 bottom
PJP302  -  [JUMP_43X118]  158.3 53.78 180 top
PJP501  JUMP_43X79  [JUMP_43X79-NPM]  198.37 70.86 0 bottom
PJP502  -  [JUMP_43X118]  221.33 79.09 270 bottom
PJP1201  JUMP_43X39  [JUMP_43X39-NPM]  58.31 42.67 0 top
PJP1202  -  [JUMP_43X79]  56.46 38.6 180 top
PJP1801  JUMP_43X39  [JUMP_43X39-NPM]  44.86 36.14 270 bottom
PJP1802  -  [JUMP_43X79]  55.41 28.42 270 bottom
PJP2501  -  [JUMP_43X39]  37.75 120.06 90 bottom
PJP2502  -  [JUMP_43X39]  26.91 122.99 180 bottom
PJPB01  JUMP_43X118  [JUMP_43X118-NPM]  185 57.38 270 bottom
PJPDC1  ACES_50458-00601-001  [ACES_50458-00601-001_6P-T]  81.2 144.05 0 bottom
PJPG1  JUMP_43X39  [JUMP_43X39-NPM]  102.35 125.79 180 bottom
PJPH01  JUMP_43X39  [JUMP_43X39-NPM]  156.75 63.13 270 bottom
PJPH02  -  [JUMP_43X118]  141.77 56.85 90 top
PJPM01  JUMP_43X39  [JUMP_43X39-NPM]  26.21 110.05 180 bottom
PJPM02  -  [JUMP_43X118]  28.31 100.58 0 top
PJPM03  -  [JUMP_43X39]  29.31 112.53 270 top
PJPZ1  JUMP_43X79  [JUMP_43X79-NPM]  87.28 125.39 270 bottom
PL1  5A Z150 20M 1210_2P  [5A_Z150_1210_2P]  90.84 145.47 0 top
PL2  5A Z150 20M 1210_2P  [5A_Z150_1210_2P]  77.34 145.17 180 bottom
PL3  BLM15AG102SN1D_2P  [MURAT_BLM15AG102SN1D_2P]  76.93 143.78 90 top
PL4  5A Z150 20M 1210_2P  [5A_Z150_1210_2P]  162.47 45.52 270 bottom
PL301  1.5UH_9A_20%_7X7X3_M  [L_7X7X3_M_2P]  161.39 59.98 270 bottom
PL311  -  [5A_Z80_0805_2P]  172.12 63.27 270 bottom
PL501  1.5UH_9A_20%_7X7X3_M  [L_7X7X3_M_2P]  210.56 79.24 0 bottom
PL511  5A Z150 20M 1210_2P  [5A_Z150_1210_2P]  197.56 70.85 0 bottom
PL1201  1UH_6.6A_20%_5X5X3_M  [L_5X5X3_M_2P]  64.95 38.22 180 bottom
PL1211  -  [5A_Z80_0805_2P]  57.92 42.67 0 top
PL1801  1UH_6.6A_20%_5X5X3_M  [L_5X5X3_M_2P]  50.88 32.44 0 bottom
PL1811  -  [5A_Z80_0805_2P]  44.86 36.53 270 bottom
PLB01  4.7UH_5.5A_20%_7X7X3_M  [L_7X7X3_M_2P]  179.96 49.04 180 bottom
PLB02  5A Z150 20M 1210_2P  [5A_Z150_1210_2P]  184.95 58.21 270 bottom
PLG1  0.24UH_22A_+-20%_7X7X3_M  [L_7X7X3_M]  93.59 113.03 0 bottom
PLG11  -  [5A_Z80_0805_2P]  102.74 125.79 180 bottom
PLH01  1UH_6.6A_20%_5X5X3_M  [L_5X5X3_M_2P]  143.44 60.98 270 bottom
